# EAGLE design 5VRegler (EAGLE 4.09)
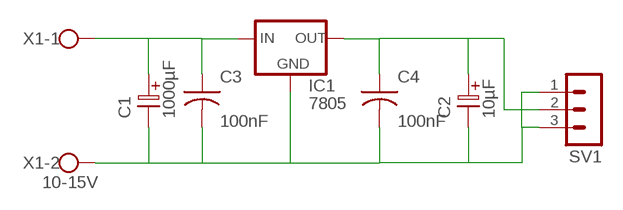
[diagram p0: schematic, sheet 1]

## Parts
C1  1000µF  ELC-5L  [ES-5L]
C2  10µF  ELC-2,5L  [ES-2,5L]
C3  100nF  CAP-5  [C-5]
C4  100nF  CAP-5  [C-5]
IC1  7805  78XXS  [78XXS]
SV1  MA03-1  [MA03-1]
X1  10-15V  W237-102  [W237-102]

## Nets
N$1: C1.1 C3.1 IC1.IN X1.1
N$3: C2.1 C4.1 IC1.OUT SV1.2
N$8: C1.2 C2.2 C3.2 C4.2 IC1.GND SV1.1 SV1.3 X1.2

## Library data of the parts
C1 = discrete:ELC-5L
C2 = discrete:ELC-2,5L
C3 C4 = discrete:CAP-5
IC1 = v-reg:78XXS: VOLTAGE REGULATOR
SV1 = con-lstb:MA03-1: PIN HEADER
X1 = con-wago-500:W237-102: WAGO SCREW CLAMP

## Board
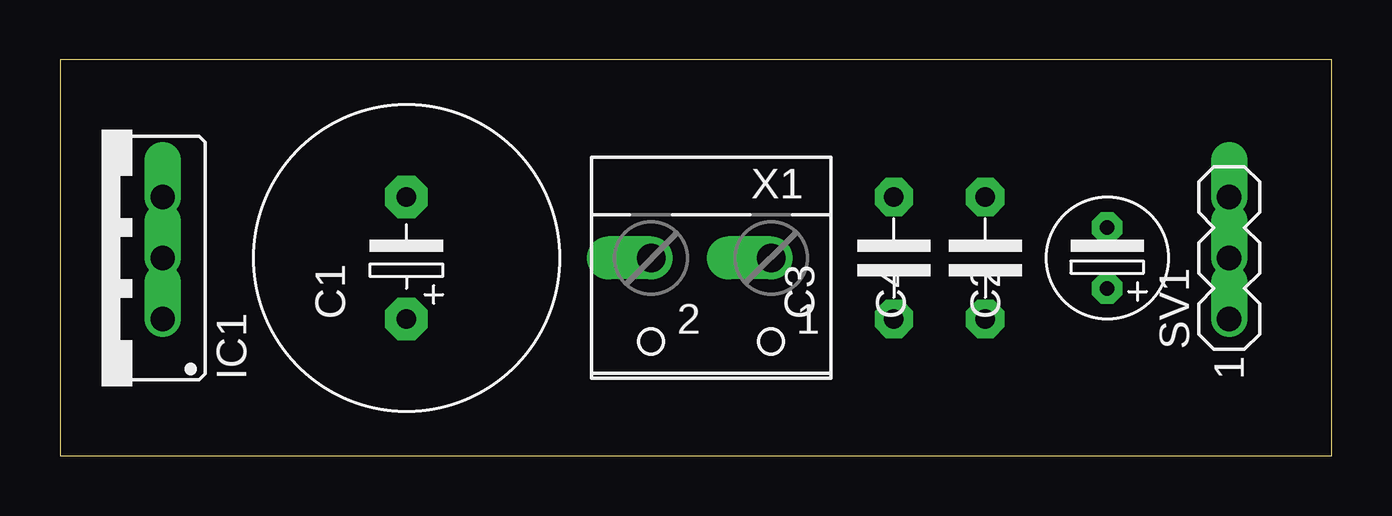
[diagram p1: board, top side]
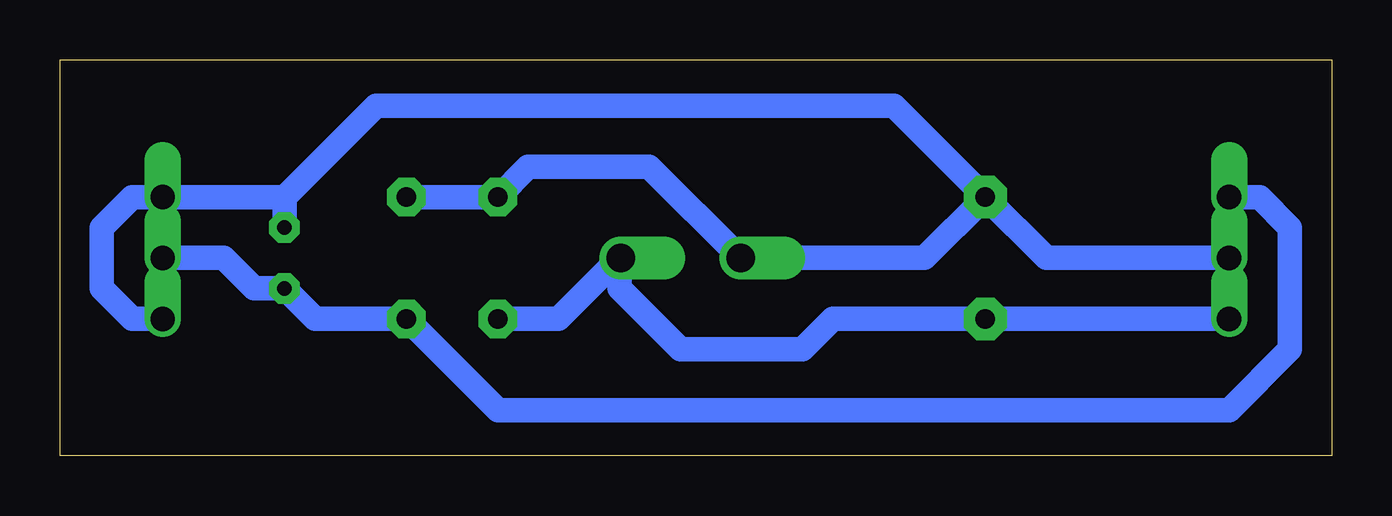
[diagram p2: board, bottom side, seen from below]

Size 53.01 x 16.5 mm. Coordinates in mm from the lower left corner, seen from the top.
Outline: 0,0 53.01,0 53.01,16.5 0,16.5 0,0
Copper layers used: Bottom

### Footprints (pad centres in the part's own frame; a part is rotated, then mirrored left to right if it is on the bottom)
ES-5L = drill 0.813 pad 1.778 octagon: 1 0,0; 2 5.08,0
ES-2,5L = drill 0.61 pad 1.27 octagon: 1 0,0; 2 2.54,0
C-5 = drill 0.813 pad 1.6 octagon: 1 -2.54,0; 2 2.54,0
78XXS = drill 1.016 offset: GND 0,-2.54; IN -2.54,-2.54; OUT 2.54,-2.54
MA03-1 = drill 1.016 offset: 1 -2.54,0; 2 0,0; 3 2.54,0
W237-102 = drill 1.194 offset: 1 -2.5,-1.27; 2 2.5,-1.27

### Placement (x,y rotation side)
C1  14.44,5.71 90 top
C2  43.65,6.98 90 top
C3  34.76,8.25 90 top
C4  38.57,8.25 90 top
IC1  1.74,8.25 90 top
SV1  48.73,8.25 90 top
X1  27.14,6.98 180 top

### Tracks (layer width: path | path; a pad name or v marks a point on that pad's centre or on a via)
N$1
  Bottom 1.016: C1.1 IC1.IN 20.79,5.71 22.06,4.44 27.14,4.44 29.68,6.98 29.68,8.25 | 29.68,8.25 X1.1 | C3.1 32.22,5.71 29.68,8.25
N$3
  Bottom 1.016: IC1.OUT 3.01,10.79 1.74,9.52 1.74,4.44 4.28,1.9 34.76,1.9 C4.1 42.38,5.71 C2.1 44.92,6.98 46.19,8.25 SV1.2
N$8
  Bottom 1.016: C1.2 16.98,8.25 X1.2 28.45,12.06 33.49,12.06 C3.2 C4.2 | IC1.GND 11.9,8.25 C1.2 | C1.2 18.25,14.6 39.84,14.6 43.65,10.79 | 43.65,10.79 C2.2 | 43.65,10.79 SV1.3 50,10.79 51.27,9.52 51.27,6.98 50,5.71 SV1.1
